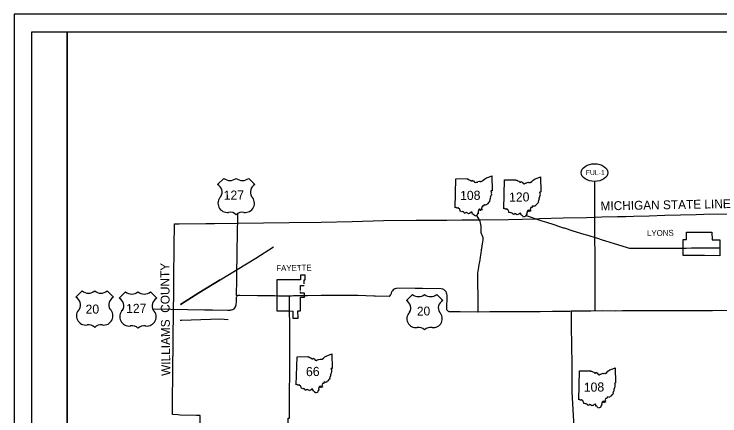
# Model space of a CAD drawing. Extents: x 0 to 849, y 0 to 440.
# Drawn here: x 0 to 399.3, y 212.6 to 440 of the extents above; entities that cross this region are included whole.
import ezdxf

# ---------------------------------------------------------------- set-up
doc = ezdxf.new("R2010")
doc.units = 0
for name, color, linetype in [('DV_X_Corp_Line', 7, 'Continuous'), ('GM_X_Adjacent_County_Text', 7, 'Continuous'), ('GM_X_Corporation_Text', 7, 'Continuous'), ('GM_X_County', 7, 'Continuous'), ('GM_X_Interstate_Route', 7, 'Continuous'), ('PV_P_Walk', 7, 'Continuous'), ('RD_X_RR_2', 7, 'Continuous'), ('SH_Border', 7, 'Continuous'), ('SH_Cut_Line', 7, 'Continuous'), ('SH_Data', 7, 'Continuous'), ('SH_Text', 7, 'Continuous')]:
    doc.layers.add(name, color=color, linetype=linetype)

msp = doc.modelspace()

# ---------------------------------------------------------------- linework, layer by layer
at = {"layer": 'DV_X_Corp_Line'}
for p, q in [((164.75, 292.15), (162.07, 292.15)), ((162.07, 292.15), (162.07, 289.66)), ((164.75, 289.68), (164.75, 292.15)), ((148.68, 289.62), (148.68, 272.1)), ((164.06, 287.31), (164.06, 289.68)), ((164.06, 289.68), (164.75, 289.68)), ((162.04, 286.33), (164.06, 286.33)), ((160.62, 267.92), (160.6, 271.96)), ((157.68, 267.9), (160.62, 267.92))]:
    msp.add_line(p, q, dxfattribs=at)
msp.add_lwpolyline([(378.46, 303.31), (378.46, 307.71), (378.42, 312.47), (380.38, 312.45), (380.36, 316.57), (385.93, 316.58), (390.38, 316.59), (394.8, 316.61), (394.82, 312.16), (399.22, 312.2), (399.27, 307.77), (399.26, 303.26), (390.51, 303.31), (382.73, 303.31)], close=True, dxfattribs=at)
for points in [[(162.07, 289.66), (148.68, 289.62)], [(162.02, 283.58), (162.04, 286.33)], [(162.08, 271.97), (162.07, 279.76), (164.31, 279.8), (164.26, 281.97), (162.08, 282.01), (162.08, 282.76)], [(148.68, 272.1), (155.87, 271.98), (157.64, 271.93), (157.68, 267.9)], [(160.6, 271.96), (162.08, 271.97)]]:
    msp.add_lwpolyline(points, dxfattribs=at)
at = {"layer": 'GM_X_County'}
msp.add_lwpolyline([(104.99, 194.86), (105.19, 212.75), (103.13, 212.74), (93.97, 213.09), (92.63, 213.14), (89.58, 213.41), (89.65, 219.9), (89.85, 237.46), (90.05, 255.11), (90.24, 272.93), (90.34, 281.47), (90.43, 290.6), (90.62, 308.28), (90.76, 321.28), (93.39, 321.36), (108.49, 321.42), (113.32, 321.44), (126.48, 321.62), (155.61, 322.01), (173.7, 322.25), (191.33, 322.68), (209.04, 323.12), (227.42, 323.33), (244.79, 323.38), (253.29, 323.48), (263.18, 323.59), (279.69, 323.78), (295.09, 324.19), (297.32, 324.25), (310.63, 324.62), (323.78, 324.97), (332.51, 325.21), (341.31, 325.4), (345.99, 325.53), (350.44, 325.66), (359.18, 325.9), (368.07, 326.15), (385.79, 326.65), (390.27, 326.72), (403.53, 326.93)], dxfattribs=at)
at = {"layer": 'GM_X_Interstate_Route'}
msp.add_line((155.85, 221.05), (155.98, 241.4), dxfattribs=at)
for points in [[(126.1, 280.44), (125.79, 280.72), (125.95, 289.76), (125.95, 289.81), (125.96, 290.09), (126.21, 307.27), (126.22, 307.72), (126.31, 313.84), (126.6, 327.41)], [(264.15, 319.33), (264.15, 319.38), (264.14, 319.92), (264.08, 320.9), (263.92, 321.89), (263.66, 322.69), (263.41, 323.18), (261.82, 326.01)], [(289.71, 326.06), (297.33, 323.41), (298.53, 323), (301.13, 322.16), (305.26, 320.84), (310.68, 319.11), (311.17, 318.96), (316.01, 317.42), (322.23, 315.52), (323.87, 315.01), (329.95, 313.12), (332.7, 312.28), (334.53, 311.72), (339.4, 310.19), (346.24, 308.03), (347.34, 307.69), (348.12, 307.52), (349.3, 307.45), (350.54, 307.45)], [(262.48, 271.57), (262.5, 273.9), (262.5, 274.97), (262.5, 275.98), (262.5, 276.16), (262.49, 277.32), (262.48, 278.49), (262.47, 279.75), (262.47, 280.41), (262.46, 280.85), (262.46, 282.11), (262.45, 283.42), (262.43, 284.75), (262.43, 285.98), (262.43, 287.21), (262.41, 288.58), (262.41, 289.22), (262.4, 289.85), (262.4, 290.97), (262.38, 292.12), (262.37, 293.4), (262.55, 294.51), (262.74, 295.71), (262.91, 296.81), (263.13, 298.21), (263.38, 299.76), (263.58, 301), (263.79, 302.46), (263.99, 303.64), (264.19, 304.89), (264.38, 306.07), (264.5, 306.85), (264.59, 307.41), (264.81, 308.74), (265, 309.95), (265.16, 311.14), (265.31, 312.23), (265.38, 313.01), (265.34, 313.48), (265.14, 313.98), (264.72, 314.83), (264.37, 315.59), (264.25, 316.19), (264.21, 317.32), (264.17, 318.69), (264.15, 319.33)], [(350.54, 307.45), (350.55, 307.45), (350.67, 307.45), (368.04, 307.57)], [(368.04, 307.57), (368.04, 307.57), (368.21, 307.57), (376.8, 307.6), (378.27, 307.6), (378.28, 307.6)], [(378.28, 307.6), (380.26, 307.61)], [(380.26, 307.61), (383.13, 307.62), (384.76, 307.63), (386.1, 307.65), (388.25, 307.67)], [(388.25, 307.67), (388.25, 307.67), (388.78, 307.68), (389.48, 307.68)], [(389.48, 307.68), (389.48, 307.68), (390.36, 307.69), (391.06, 307.7)], [(391.06, 307.7), (391.07, 307.7), (392.1, 307.71), (392.29, 307.71)], [(392.29, 307.71), (392.29, 307.71), (394.11, 307.73), (395.71, 307.75), (395.96, 307.75), (399.29, 307.79), (399.29, 307.79)], [(230.88, 284.9), (216.23, 284.71), (215.57, 284.52), (215.4, 284.45), (214.95, 284.26), (214.5, 283.91), (214.04, 283.46), (213.69, 282.97), (213.39, 282.28), (213.23, 281.68), (213.17, 281.29)], [(226.96, 284.9), (241.61, 284.71), (242.27, 284.52), (242.44, 284.45), (242.89, 284.26), (243.34, 283.91), (243.8, 283.46), (244.15, 282.97), (244.45, 282.28), (244.61, 281.68), (244.72, 280.95), (244.74, 280.47), (244.7, 273.06), (244.83, 272.69), (245.13, 272.23), (245.53, 271.83), (245.97, 271.6), (252.38, 271.61), (262.3, 271.57)], [(125.65, 275.38), (125.68, 275.45), (125.74, 277.32), (125.79, 279.71), (125.93, 280.08), (126.1, 280.44)], [(126.1, 280.44), (126.24, 280.58), (126.45, 280.77), (126.73, 280.9), (127.16, 280.95), (127.53, 280.95), (127.72, 280.94)], [(127.72, 280.94), (137.62, 280.8), (146.79, 280.66), (146.85, 280.66)], [(146.85, 280.66), (147.25, 280.66), (149.53, 280.63)], [(149.53, 280.63), (149.67, 280.63), (150.76, 280.61), (152.6, 280.59), (153.65, 280.58)], [(153.65, 280.58), (153.67, 280.58), (154.72, 280.59)], [(154.72, 280.59), (154.73, 280.59), (155.79, 280.61)], [(155.79, 280.61), (155.79, 280.61), (156.85, 280.63)], [(155.79, 280.07), (155.79, 280.07), (155.79, 280.61)], [(155.8, 279), (155.8, 279), (155.8, 279.46), (155.79, 280.07)], [(156.85, 280.63), (156.92, 280.63), (157.97, 280.65), (159.02, 280.66), (162.5, 280.71)], [(162.5, 280.71), (162.57, 280.71), (164.61, 280.73)], [(164.61, 280.73), (165.92, 280.75), (173.79, 280.87), (174.5, 280.88)], [(174.5, 280.88), (174.66, 280.88), (184.29, 280.94), (191.47, 280.96), (194.39, 280.93), (203.42, 280.63), (204.29, 280.62), (212.16, 280.44)], [(155.85, 271.69), (155.84, 272.66), (155.81, 277.86), (155.81, 278.34), (155.8, 278.97), (155.8, 279)], [(78.97, 273.11), (107.77, 272.65), (112.26, 272.58), (120.97, 272.41), (122.03, 272.45), (122.16, 272.48), (122.31, 272.51)], [(122.31, 272.51), (122.52, 272.55), (122.97, 272.62), (123.76, 272.87), (124.4, 273.26), (124.87, 273.8), (125.26, 274.4), (125.65, 275.38)], [(155.9, 267.83), (155.9, 267.95), (155.88, 268.71), (155.85, 271.69)], [(262.3, 271.57), (262.48, 271.57), (269.1, 271.59), (279.93, 271.64), (284.28, 271.65), (290.75, 271.71), (297.66, 271.76), (304.64, 271.83), (309.05, 271.89)], [(309.05, 271.89), (311.68, 271.92), (311.68, 271.92)], [(311.68, 271.92), (313.25, 271.94), (314.3, 271.95), (315.33, 271.97), (315.51, 271.97)], [(315.73, 226.19), (315.7, 229.72), (315.65, 236.11), (315.65, 236.55), (315.62, 244.09), (315.51, 250.16), (315.46, 254.17), (315.39, 261.62), (315.35, 268.58), (315.35, 269.75), (315.33, 271.97)], [(315.51, 271.97), (324.16, 272.07), (326, 272.09), (326.28, 272.09)], [(326.28, 272.09), (332.98, 272.15), (340.32, 272.06), (344.27, 272.15), (346.61, 272.16), (351.08, 272.15), (358.34, 272.18), (366.67, 272.21), (368.5, 272.22), (377.41, 272.27), (385.4, 272.28), (390.75, 272.3), (391.52, 272.3), (395.11, 272.33), (403.95, 272.4), (411.47, 272.38), (412.84, 272.38), (413.53, 272.38)], [(155.98, 241.4), (155.98, 241.48), (155.98, 243.65), (155.96, 253.99), (155.95, 258.22), (155.91, 266.4), (155.9, 267.83)], [(317.06, 190.95), (317.12, 194.28), (317.22, 199.46), (315.73, 226.19)], [(154.66, 192.87), (154.66, 192.98), (154.68, 193.88), (154.9, 204.94), (155.08, 211.05), (155.13, 211.21), (155.24, 211.26), (155.71, 211.25), (155.78, 211.33), (155.76, 212.2), (155.8, 216.41), (155.83, 218.75), (155.85, 221.05)]]:
    msp.add_lwpolyline(points, dxfattribs=at)
msp.add_arc((212.18, 281.44), 1, 268.7437, 351.1773, dxfattribs=at)
at = {"layer": 'PV_P_Walk'}
for p, q in [((118.61, 347.04), (115.07, 343.5)), ((136.25, 343.5), (132.7, 347.04)), ((249.52, 330.4), (249.97, 346.78)), ((277.04, 329.77), (277.5, 346.14)), ((38.53, 283.29), (34.98, 279.74)), ((38.53, 283.29), (34.98, 279.74)), ((56.17, 279.74), (52.62, 283.29)), ((56.17, 279.74), (52.62, 283.29)), ((63.03, 282.76), (59.49, 279.22)), ((63.03, 282.76), (59.49, 279.22)), ((80.67, 279.22), (77.13, 282.76)), ((80.67, 279.22), (77.13, 282.76)), ((225.36, 281.29), (221.92, 277.85)), ((242.51, 277.85), (239.06, 281.29)), ((159.66, 230.17), (160.11, 246.08)), ((319.41, 221.67), (319.86, 238.05))]:
    msp.add_line(p, q, dxfattribs=at)
for points in [[(249.97, 346.78), (256.33, 346.88), (256.23, 346.69), (256.83, 346.64), (257.46, 346.29), (258, 346.07), (258.66, 345.55), (259.05, 345.56), (259.22, 345.99), (259.52, 345.66), (259.88, 345.6), (260.5, 344.81), (261.01, 344.64), (261.62, 344.91), (262.08, 344.96), (262.42, 345.22), (263.29, 345.45), (263.53, 345.31), (263.99, 345.34), (264.22, 345.44), (264.63, 345.35), (265.34, 345.95), (266.07, 346.65), (267.19, 347.31), (268.86, 347.94), (270.19, 348.5), (270.38, 340)], [(277.5, 346.14), (283.85, 346.25), (283.75, 346.05), (284.35, 346.01), (284.99, 345.66), (285.53, 345.44), (286.18, 344.92), (286.58, 344.93), (286.75, 345.35), (287.05, 345.02), (287.41, 344.96), (288.02, 344.18), (288.54, 344.01), (289.15, 344.28), (289.61, 344.32), (289.94, 344.59), (290.81, 344.82), (291.06, 344.68), (291.52, 344.71), (291.75, 344.81), (292.15, 344.72), (292.86, 345.31), (293.59, 346.02), (294.71, 346.68), (296.39, 347.31), (297.71, 347.87), (297.9, 339.37)], [(270.38, 340), (270.18, 339.88), (269.88, 339.94), (269.68, 339.7), (269.93, 339.3), (270.05, 338.88), (269.94, 338.42), (270.05, 338.04), (269.98, 337.72), (269.78, 337.4), (269.72, 337.1), (269.56, 336.78), (269.57, 336.6), (269.41, 336.46), (269.44, 335.93), (269.36, 335.63), (269.39, 335.38), (269.14, 335.31), (269.2, 335.1), (269.04, 334.94), (269.07, 334.66), (268.89, 334.48), (269.07, 334.13), (268.92, 334.01), (268.81, 333.58), (268.48, 333.49), (267.84, 332.7), (267.61, 332.4), (267.35, 332.32), (267.21, 332.02), (266.9, 332.02), (266.42, 331.8), (266.11, 332.17), (265.57, 331.73), (265.51, 331.22), (264.83, 331.23), (264.85, 330.97), (264.7, 330.9), (264.56, 330.64), (264.64, 330.18), (264.32, 330.06), (264.36, 329.8), (264.57, 329.63), (264.66, 329.12), (264.32, 329.23), (264.04, 328.8), (263.75, 328.9), (263.85, 329.26), (263.36, 329.7), (262.9, 329.35), (262.66, 328.79), (262.66, 328.41), (262.32, 328.19), (262.54, 327.65), (262.5, 327.29), (262.51, 326.94), (262.08, 326.95), (261.82, 326.01)], [(297.9, 339.37), (297.71, 339.25), (297.4, 339.31), (297.2, 339.07), (297.45, 338.67), (297.57, 338.25), (297.47, 337.79), (297.57, 337.41), (297.5, 337.09), (297.31, 336.77), (297.24, 336.46), (297.08, 336.15), (297.09, 335.97), (296.94, 335.82), (296.97, 335.29), (296.89, 335), (296.92, 334.74), (296.66, 334.68), (296.72, 334.47), (296.56, 334.31), (296.6, 334.03), (296.41, 333.85), (296.59, 333.49), (296.45, 333.38), (296.33, 332.95), (296.01, 332.86), (295.36, 332.07), (295.13, 331.77), (294.88, 331.69), (294.74, 331.38), (294.42, 331.38), (293.95, 331.17), (293.64, 331.54), (293.1, 331.09), (293.03, 330.58), (292.35, 330.6), (292.38, 330.34), (292.22, 330.27), (292.09, 330.01), (292.17, 329.55), (291.85, 329.43), (291.89, 329.16), (292.09, 329), (292.18, 328.49), (291.84, 328.59), (291.56, 328.16), (291.28, 328.27), (291.37, 328.63), (290.89, 329.07), (290.43, 328.72), (290.19, 328.16), (290.19, 327.78), (289.85, 327.55), (290.06, 327.02), (290.02, 326.65), (290.03, 326.3), (289.6, 326.32), (289.35, 325.38)], [(261.82, 326.01), (261.08, 325.83), (260.57, 325.72), (260.38, 326.15), (260.02, 326.37), (259.78, 326.8), (259.25, 326.86), (259.12, 327.45), (259.06, 327.93), (258.34, 327.81), (258.14, 327.52), (257.89, 327.44), (257.74, 327.15), (257.39, 327.12), (257.01, 326.98), (256.77, 327.27), (256.15, 327.56), (255.88, 327.71), (255.3, 327.48), (255.18, 327.21), (254.72, 327.33), (254.61, 327.63), (254.33, 327.73), (254.27, 328.05), (253.68, 328.23), (253.22, 328.16), (252.42, 328.42), (252.37, 328.85), (252.1, 329.37), (251.96, 329.73), (251.45, 330.01), (251.35, 330.44), (251.18, 330.43), (251.04, 330.26), (250.47, 330.18), (250.25, 330.35), (249.93, 330.65), (249.52, 330.4)], [(289.35, 325.38), (288.6, 325.2), (288.09, 325.09), (287.91, 325.52), (287.54, 325.74), (287.3, 326.17), (286.77, 326.23), (286.65, 326.82), (286.59, 327.3), (285.87, 327.18), (285.67, 326.89), (285.41, 326.81), (285.26, 326.51), (284.91, 326.49), (284.54, 326.35), (284.29, 326.64), (283.68, 326.93), (283.4, 327.08), (282.83, 326.85), (282.7, 326.57), (282.24, 326.69), (282.13, 327), (281.86, 327.09), (281.8, 327.42), (281.2, 327.59), (280.75, 327.52), (279.94, 327.79), (279.9, 328.22), (279.62, 328.74), (279.48, 329.1), (278.97, 329.38), (278.87, 329.81), (278.71, 329.8), (278.56, 329.62), (278, 329.54), (277.77, 329.72), (277.46, 330.02), (277.04, 329.77)], [(160.11, 246.08), (166.28, 246.19), (166.19, 245.99), (166.77, 245.95), (167.39, 245.61), (167.91, 245.4), (168.55, 244.89), (168.93, 244.9), (169.1, 245.31), (169.39, 244.99), (169.74, 244.94), (170.34, 244.18), (170.84, 244.01), (171.43, 244.27), (171.88, 244.31), (172.2, 244.57), (173.05, 244.79), (173.29, 244.66), (173.73, 244.69), (173.96, 244.79), (174.35, 244.7), (175.04, 245.28), (175.75, 245.96), (176.84, 246.6), (178.47, 247.21), (179.76, 247.76), (179.94, 239.5)], [(319.86, 238.05), (326.22, 238.15), (326.12, 237.95), (326.72, 237.91), (327.35, 237.56), (327.89, 237.34), (328.55, 236.82), (328.95, 236.83), (329.11, 237.25), (329.41, 236.93), (329.77, 236.87), (330.39, 236.08), (330.9, 235.91), (331.51, 236.18), (331.97, 236.23), (332.31, 236.49), (333.18, 236.72), (333.42, 236.58), (333.88, 236.61), (334.12, 236.71), (334.52, 236.62), (335.23, 237.22), (335.96, 237.92), (337.08, 238.58), (338.75, 239.21), (340.08, 239.77), (340.27, 231.27)], [(179.94, 239.5), (179.75, 239.38), (179.46, 239.44), (179.26, 239.21), (179.5, 238.82), (179.62, 238.41), (179.52, 237.96), (179.62, 237.59), (179.55, 237.28), (179.36, 236.97), (179.3, 236.68), (179.14, 236.36), (179.15, 236.19), (179, 236.05), (179.03, 235.54), (178.96, 235.25), (178.98, 235), (178.74, 234.94), (178.79, 234.73), (178.64, 234.58), (178.67, 234.31), (178.49, 234.13), (178.67, 233.79), (178.53, 233.68), (178.41, 233.26), (178.1, 233.17), (177.47, 232.4), (177.25, 232.11), (177, 232.04), (176.86, 231.74), (176.56, 231.73), (176.09, 231.53), (175.79, 231.88), (175.27, 231.45), (175.21, 230.96), (174.54, 230.97), (174.57, 230.72), (174.42, 230.65), (174.29, 230.4), (174.37, 229.95), (174.05, 229.84), (174.09, 229.58), (174.29, 229.42), (174.38, 228.93), (174.05, 229.03), (173.78, 228.61), (173.5, 228.71), (173.59, 229.06), (173.12, 229.49), (172.68, 229.14), (172.44, 228.6), (172.44, 228.23), (172.11, 228.01), (172.32, 227.49), (172.28, 227.14), (172.29, 226.8), (171.87, 226.81), (171.62, 225.9)], [(171.62, 225.9), (170.9, 225.72), (170.4, 225.62), (170.23, 226.03), (169.87, 226.25), (169.64, 226.67), (169.12, 226.73), (169, 227.3), (168.94, 227.77), (168.24, 227.65), (168.05, 227.37), (167.8, 227.29), (167.65, 227), (167.31, 226.98), (166.95, 226.84), (166.71, 227.13), (166.12, 227.41), (165.85, 227.55), (165.29, 227.33), (165.17, 227.06), (164.72, 227.18), (164.61, 227.48), (164.34, 227.57), (164.28, 227.88), (163.71, 228.05), (163.26, 227.99), (162.49, 228.24), (162.44, 228.66), (162.17, 229.17), (162.03, 229.52), (161.54, 229.79), (161.44, 230.21), (161.28, 230.19), (161.14, 230.02), (160.59, 229.95), (160.37, 230.12), (160.07, 230.41), (159.66, 230.17)], [(340.27, 231.27), (340.08, 231.15), (339.77, 231.21), (339.57, 230.97), (339.82, 230.57), (339.94, 230.15), (339.83, 229.69), (339.94, 229.31), (339.87, 228.99), (339.67, 228.67), (339.61, 228.37), (339.45, 228.05), (339.46, 227.87), (339.3, 227.73), (339.33, 227.2), (339.25, 226.9), (339.28, 226.65), (339.03, 226.58), (339.09, 226.37), (338.93, 226.21), (338.96, 225.93), (338.78, 225.75), (338.96, 225.4), (338.82, 225.28), (338.7, 224.85), (338.37, 224.76), (337.73, 223.97), (337.5, 223.67), (337.24, 223.59), (337.1, 223.29), (336.79, 223.28), (336.31, 223.07), (336, 223.44), (335.46, 223), (335.4, 222.49), (334.72, 222.5), (334.74, 222.24), (334.59, 222.17), (334.45, 221.91), (334.53, 221.45), (334.21, 221.33), (334.25, 221.07), (334.46, 220.9), (334.55, 220.39), (334.21, 220.5), (333.93, 220.07), (333.64, 220.17), (333.74, 220.53), (333.25, 220.97), (332.79, 220.62), (332.56, 220.06), (332.55, 219.68), (332.21, 219.45), (332.43, 218.92), (332.39, 218.55), (332.4, 218.21), (331.97, 218.22), (331.71, 217.28)], [(331.71, 217.28), (330.97, 217.1), (330.46, 216.99), (330.27, 217.42), (329.91, 217.64), (329.67, 218.07), (329.14, 218.13), (329.01, 218.72), (328.95, 219.2), (328.23, 219.08), (328.03, 218.79), (327.78, 218.71), (327.63, 218.42), (327.28, 218.39), (326.9, 218.25), (326.66, 218.54), (326.04, 218.83), (325.77, 218.98), (325.19, 218.75), (325.07, 218.47), (324.61, 218.6), (324.5, 218.9), (324.22, 219), (324.16, 219.32), (323.57, 219.5), (323.11, 219.43), (322.31, 219.69), (322.26, 220.12), (321.99, 220.64), (321.85, 221), (321.34, 221.28), (321.24, 221.71), (321.07, 221.7), (320.93, 221.52), (320.36, 221.44), (320.14, 221.62), (319.82, 221.92), (319.41, 221.67)]]:
    msp.add_lwpolyline(points, dxfattribs=at)
for centre, radius, start, end in [((112.85, 339.22), 4.82, 329.1175, 62.6108), ((122.13, 351.52), 5.7, 231.813, 308.187), ((129.18, 351.52), 5.7, 231.813, 308.187), ((138.47, 339.22), 4.82, 117.3892, 210.8825), ((120.53, 332.94), 5.2, 133.0046, 278.7282), ((130.78, 332.94), 5.2, 261.2718, 46.9954), ((122.28, 323.25), 4.65, 43.4177, 101.8742), ((129.13, 322.94), 4.94, 79.9613, 134.7468), ((32.77, 275.46), 4.82, 329.1175, 62.6108), ((42.05, 287.76), 5.7, 231.813, 308.187), ((49.1, 287.76), 5.7, 231.813, 308.187), ((58.38, 275.46), 4.82, 117.3892, 210.8825), ((66.56, 287.24), 5.7, 231.813, 308.187), ((73.6, 287.24), 5.7, 231.813, 308.187), ((228.79, 285.65), 5.54, 231.813, 308.187), ((235.64, 285.65), 5.54, 231.813, 308.187), ((57.27, 274.94), 4.82, 329.1175, 62.6108), ((82.89, 274.94), 4.82, 117.3892, 210.8825), ((219.76, 273.69), 4.68, 329.1175, 62.6108), ((244.66, 273.69), 4.68, 117.3892, 210.8825), ((40.45, 269.18), 5.2, 133.0046, 278.7282), ((50.7, 269.18), 5.2, 261.2718, 46.9954), ((64.96, 268.66), 5.2, 133.0046, 278.7282), ((75.21, 268.66), 5.2, 261.2718, 46.9954), ((227.23, 267.59), 5.05, 133.0046, 278.7282), ((237.19, 267.59), 5.05, 261.2718, 46.9954), ((42.2, 259.49), 4.65, 43.4177, 101.8742), ((49.05, 259.18), 4.94, 79.9613, 134.7468), ((66.7, 258.97), 4.65, 43.4177, 101.8742), ((73.56, 258.66), 4.94, 79.9613, 134.7468), ((228.93, 258.17), 4.52, 43.4177, 101.8742), ((235.59, 257.87), 4.8, 79.9613, 134.7468)]:
    msp.add_arc(centre, radius, start, end, dxfattribs=at)
at = {"layer": 'RD_X_RR_2'}
for points in [[(116.53, 289.59), (136.68, 301.94), (146.74, 308.22), (146.74, 308.2)], [(116.53, 289.59), (136.68, 301.94), (146.74, 308.22), (146.74, 308.2)], [(116.53, 289.59), (104.55, 282.26), (94.2, 275.71), (94.09, 275.71)], [(94.09, 275.71), (94.2, 275.71), (104.55, 282.26), (116.53, 289.59)], [(93.91, 266.86), (94.65, 266.86), (116.48, 267.47), (121.01, 267.06)], [(93.91, 266.86), (94.65, 266.86), (116.48, 267.47), (121.01, 267.06)]]:
    msp.add_lwpolyline(points, dxfattribs=at)
at = {"layer": 'SH_Border'}
for points in [[(10, 430), (30, 430), (30, 10), (10, 10)], [(30, 430), (670, 430), (670, 10), (30, 10)]]:
    msp.add_lwpolyline(points, close=True, dxfattribs=at)
at = {"layer": 'SH_Cut_Line'}
msp.add_lwpolyline([(0, 0), (680, 0), (680, 440), (0, 440)], close=True, dxfattribs=at)
at = {"layer": 'SH_Data'}
msp.add_line((315.51, 271.97), (391.52, 272.3), dxfattribs=at)
at = {"layer": 'SH_Text'}
msp.add_line((328.36, 345.29), (328.48, 272.03), dxfattribs=at)
msp.add_ellipse((328.36, 350.29), major_axis=(7.5, 0), ratio=0.666667, dxfattribs=at)

# ---------------------------------------------------------------- texts
at = {"layer": 'GM_X_Adjacent_County_Text'}
for s, rotation, p in [('MICHIGAN STATE LINE', 1.0142, (331.8, 328.91)), ('WILLIAMS  COUNTY', 90.6034, (88.39, 235.26))]:
    msp.add_text(s, height=5.0058, rotation=rotation, dxfattribs=at).set_placement(p)
at = {"layer": 'GM_X_Corporation_Text'}
for s, p in [('LYONS', (358.1, 314.31)), ('FAYETTE', (148.34, 294.51))]:
    msp.add_text(s, height=3.325, rotation=1.0142, dxfattribs=at).set_placement(p)
at = {"layer": 'PV_P_Walk'}
for s, height, p in [('127', 5.162, (118.61, 334.87)), ('108', 5.162, (252.35, 334.72)), ('120', 5.162, (280.06, 333.79)), ('20', 5.162, (40.46, 270.36)), ('127', 5.162, (63.39, 270.74)), ('20', 5.018, (227.95, 269.34)), ('66', 5.162, (165.17, 235.06)), ('108', 5.162, (322.33, 226.21))]:
    msp.add_text(s, height=height, rotation=1.0142, dxfattribs=at).set_placement(p)
at = {"layer": 'SH_Text'}
msp.add_text('FUL-1', height=2.8, dxfattribs=at).set_placement((323.41, 348.89))

doc.saveas('drawing.dxf')
